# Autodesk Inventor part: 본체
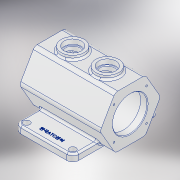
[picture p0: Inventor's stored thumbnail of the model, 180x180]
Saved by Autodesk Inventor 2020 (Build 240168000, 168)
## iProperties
Created: 2021-06
Part Number: 본체
Material: 알루미늄 6061
Document SubType Name: Modeling
Designer: 605-13
Density: 2.7 g/cm^3
Appearance: 알루미늄 - 평지
Mass: 1495.28 g
Surface Area: 1102.35 cm^2
Volume: 553.807 cm^3
Author: 605-13
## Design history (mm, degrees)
sketch "스케치1"
  geometry: L1 (-70, 0)-(70, 0); L2 (-70, 52.5)-(70, 52.5); L3 (70, 52.5)-(70, 30); L4 (70, 30)-(58, 30); L5 (58, 30)-(58, 37.5); L6 (58, 37.5)-(-58, 37.5); L7 (-58, 37.5)-(-58, 30); L8 (-58, 30)-(-70, 30); L9 (-70, 30)-(-70, 52.5); 1 further point
  constraints: 18 end point, 6 perpendicular, 2 horizontal, 2 point on line, 2 vertical alignment, 1 collinear, 1 midpoint
  dimensions: "d0" = 140 distance of L1.start L1.end; "d1" = 70 distance of L1.end point (0, 0); "d2" = 60 diameter of L8 L1; "d3" = 75 diameter of L6 L1; "d4" = 105 diameter of L2 L1; "d5" = 12 distance of L7.end L8.end
revolve "회전1" sketch "스케치1" stored, may be unused: angle "d6" = 90 deg
sketch "스케치2"
  geometry: L1 (52.5, 0)-(26.25, -45.466); L2 (26.25, -45.466)-(-26.25, -45.466); L3 (-26.25, -45.466)-(-52.5, 0); L4 (-52.5, 0)-(-26.25, 45.466); L5 (-26.25, 45.466)-(26.25, 45.466); L6 (26.25, 45.466)-(52.5, 0); C1 r 52.5 at (0, 0) reference; 15 further points
  constraints: 12 end point, 2 horizontal alignment, 1 coincident, 14 other
extrude "돌출1" cut sketch "스케치2" extent not by distance; stored distance "d7" = 0; taper "d8" = 0 deg
node "작업 평면2"
sketch "스케치5"
  geometry: L1 (45, -75)-(-55, -75); L2 (-55, -75)-(-55, 75); L3 (-55, 75)-(45, 75); L4 (45, 75)-(45, -75); L5 (70, -26.25)-(70, -52.5) reference; 1 further point
  constraints: 8 end point, 2 parallel, 1 horizontal, 1 perpendicular
  dimensions: "d23" = 150 distance of L1.end L2.end; "d24" = 75 distance from line of point (0, 0) L1; "d25" = 25 distance between parallel lines of L5 L4; "d26" = 100 distance of L1.start L1.end
extrude "돌출3" join sketch "스케치5" distance "d27" = 12; taper "d28" = 0 deg
sketch "스케치6"
  geometry: L1 (55, 75)-(-45, 75) reference; L2 (-45, 75)-(-45, 30.561) reference; L3 (55, 30.561)-(55, 75) reference; L4 (-45, -75)-(55, -75) reference; 5 further points
  constraints: 2 horizontal alignment, 2 vertical alignment
  dimensions: "d29" = 10 distance from line of L1 point (-35, 65); "d30" = 10 distance from line of L2 point (-35, 65); "d31" = 10 distance from line of L3 point (45, 65); "d32" = 10 distance from line of L4 point (45, -65)
hole "구멍2" sketch "스케치6" at (-35, 65), (45, 65), (45, -65), (-35, -65) diameter "d33" = 11; stored, may be unused: countersink angle "d37" = 90 deg, drill point angle "d39" = 0 deg; dims "d34" = 6, "d35" = 30, "d36" = 8, "d38" = 32
sketch "스케치7" dims "d40" = 80
  geometry: 3 further points
  constraints: 2 vertical alignment, 1 coincident, 2 other
hole "구멍3" sketch "스케치7" at (26.25, -5.466) diameter "d41" = 3.242; stored, may be unused: countersink angle "d45" = 90 deg, drill point angle "d47" = 120 deg; dims "d42" = 8, "d43" = 30, "d44" = 8, "d46" = 10
sketch "스케치8" dims "d51" = 80
  geometry: L1 (-13.75, 45.466)-(26.25, 45.466); L2 (26.25, 45.466)-(-2.034, 73.751); C1 r 1.621 at (-13.75, 45.466) reference; 2 further points
  constraints: 4 end point, 2 coincident, 1 horizontal, 3 other
  dimensions: "d52" = 45 deg angle of L1 L2
hole "구멍4" sketch "스케치8" at (-2.034, 73.751) diameter "d53" = 3.242; stored, may be unused: countersink angle "d57" = 90 deg, drill point angle "d59" = 120 deg; dims "d54" = 8, "d55" = 30, "d56" = 8, "d58" = 10
sketch "스케치9"
  geometry: L1 (-45, 75)-(-45, 30.561) reference; L2 (55, 75)-(-45, 75) reference; 2 further points
  constraints: 1 other
  dimensions: "d63" = 50 distance from line of L1 point (5, 61); "d64" = 14 distance from line of L2 point (5, 61)
feature "엠보싱1" sketch "스케치9" dims "d0" = 140, "d1" = 70, "d2" = 60, "d3" = 75, "d4" = 105, "d5" = 12, "d65" = 0.5, "d66" = 0
fillet "모깎기1" dims "d67" = 10
fillet "모깎기2" dims "d68" = 3
fillet "모깎기3" dims "d69" = 8
fillet "모깎기4" dims "d70" = 3
chamfer "모따기1" distance "d72" = 1; stored, may be unused: second distance "d73" = 2, angle "d74" = 45 deg
fillet "모깎기6" dims "d75" = 5
node "작업 평면3"
sketch "스케치10"
  geometry: L1 (-70, -21.631)-(-70, 21.631) reference; C1 r 20 at (-30, 0); C2 r 20 at (30, 0); 1 further point
  constraints: 2 centre point, 2 horizontal alignment
  dimensions: "d80" = 40 diameter of C1; "d81" = 40 diameter of C2; "d82" = 60 distance of C2.centre C1.centre; "d83" = 40 distance from line of L1 C1.centre
extrude "돌출4" join sketch "스케치10" stored distance "d84" = 12; taper "d85" = 0 deg
sketch "스케치11"
  geometry: C1 r 20 at (0, 0) reference; C2 r 20 at (-60, 0) reference; 3 further points
  constraints: 2 coincident
hole "구멍5" sketch "스케치11" at (0, 0), (-60, 0) diameter "d86" = 25; stored, may be unused: countersink angle "d90" = 90 deg, drill point angle "d92" = 0 deg; dims "d87" = 8, "d88" = 30, "d89" = 8, "d91" = 29
fillet "모깎기7" dims "d93" = 3
chamfer "모따기3" distance "d94" = 1; stored, may be unused: second distance "d95" = 2, angle "d96" = 45 deg
node "솔리드1"
pattern_circular "원형 패턴1" dims angle "d49" = 360 deg
pattern_circular "원형 패턴2" dims angle "d61" = 360 deg
feature "A9D066F2-1C7D-4E18-AEED-F7BC21143FA4" dims "d33" = 11, "d34" = 6, "d35" = 30, "d36" = 8, "d37" = 90 deg, "d38" = 32, "d39" = 0
other parameters: "d79" = 52.5
